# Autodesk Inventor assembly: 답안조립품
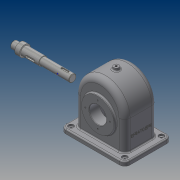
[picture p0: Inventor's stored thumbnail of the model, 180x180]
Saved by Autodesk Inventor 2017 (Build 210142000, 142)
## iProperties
Part Number: 답안조립품
Material: 일반
Document SubType Name: Assembly
Designer: 20
Author: 20
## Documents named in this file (3)
- C:\Users\20\Desktop\480310V1010\답안조립품.iam
- C:\Users\20\Desktop\480310V1010\본체.ipt
- C:\Users\20\Desktop\480310V1010\축.ipt
